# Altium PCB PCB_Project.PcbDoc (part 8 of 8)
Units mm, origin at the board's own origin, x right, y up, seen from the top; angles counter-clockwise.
Board outline 250 x 200 mm, 6 copper layers (Top Shielding/Sig, Sig 1, PWR, GND, Sig 4, Bottom Shielding/Sig), stack 1.568 mm thick; 736 components, 420 nets, 1929 pads, 2185 vias.
Unrouted connection lines stored in the file: 47.
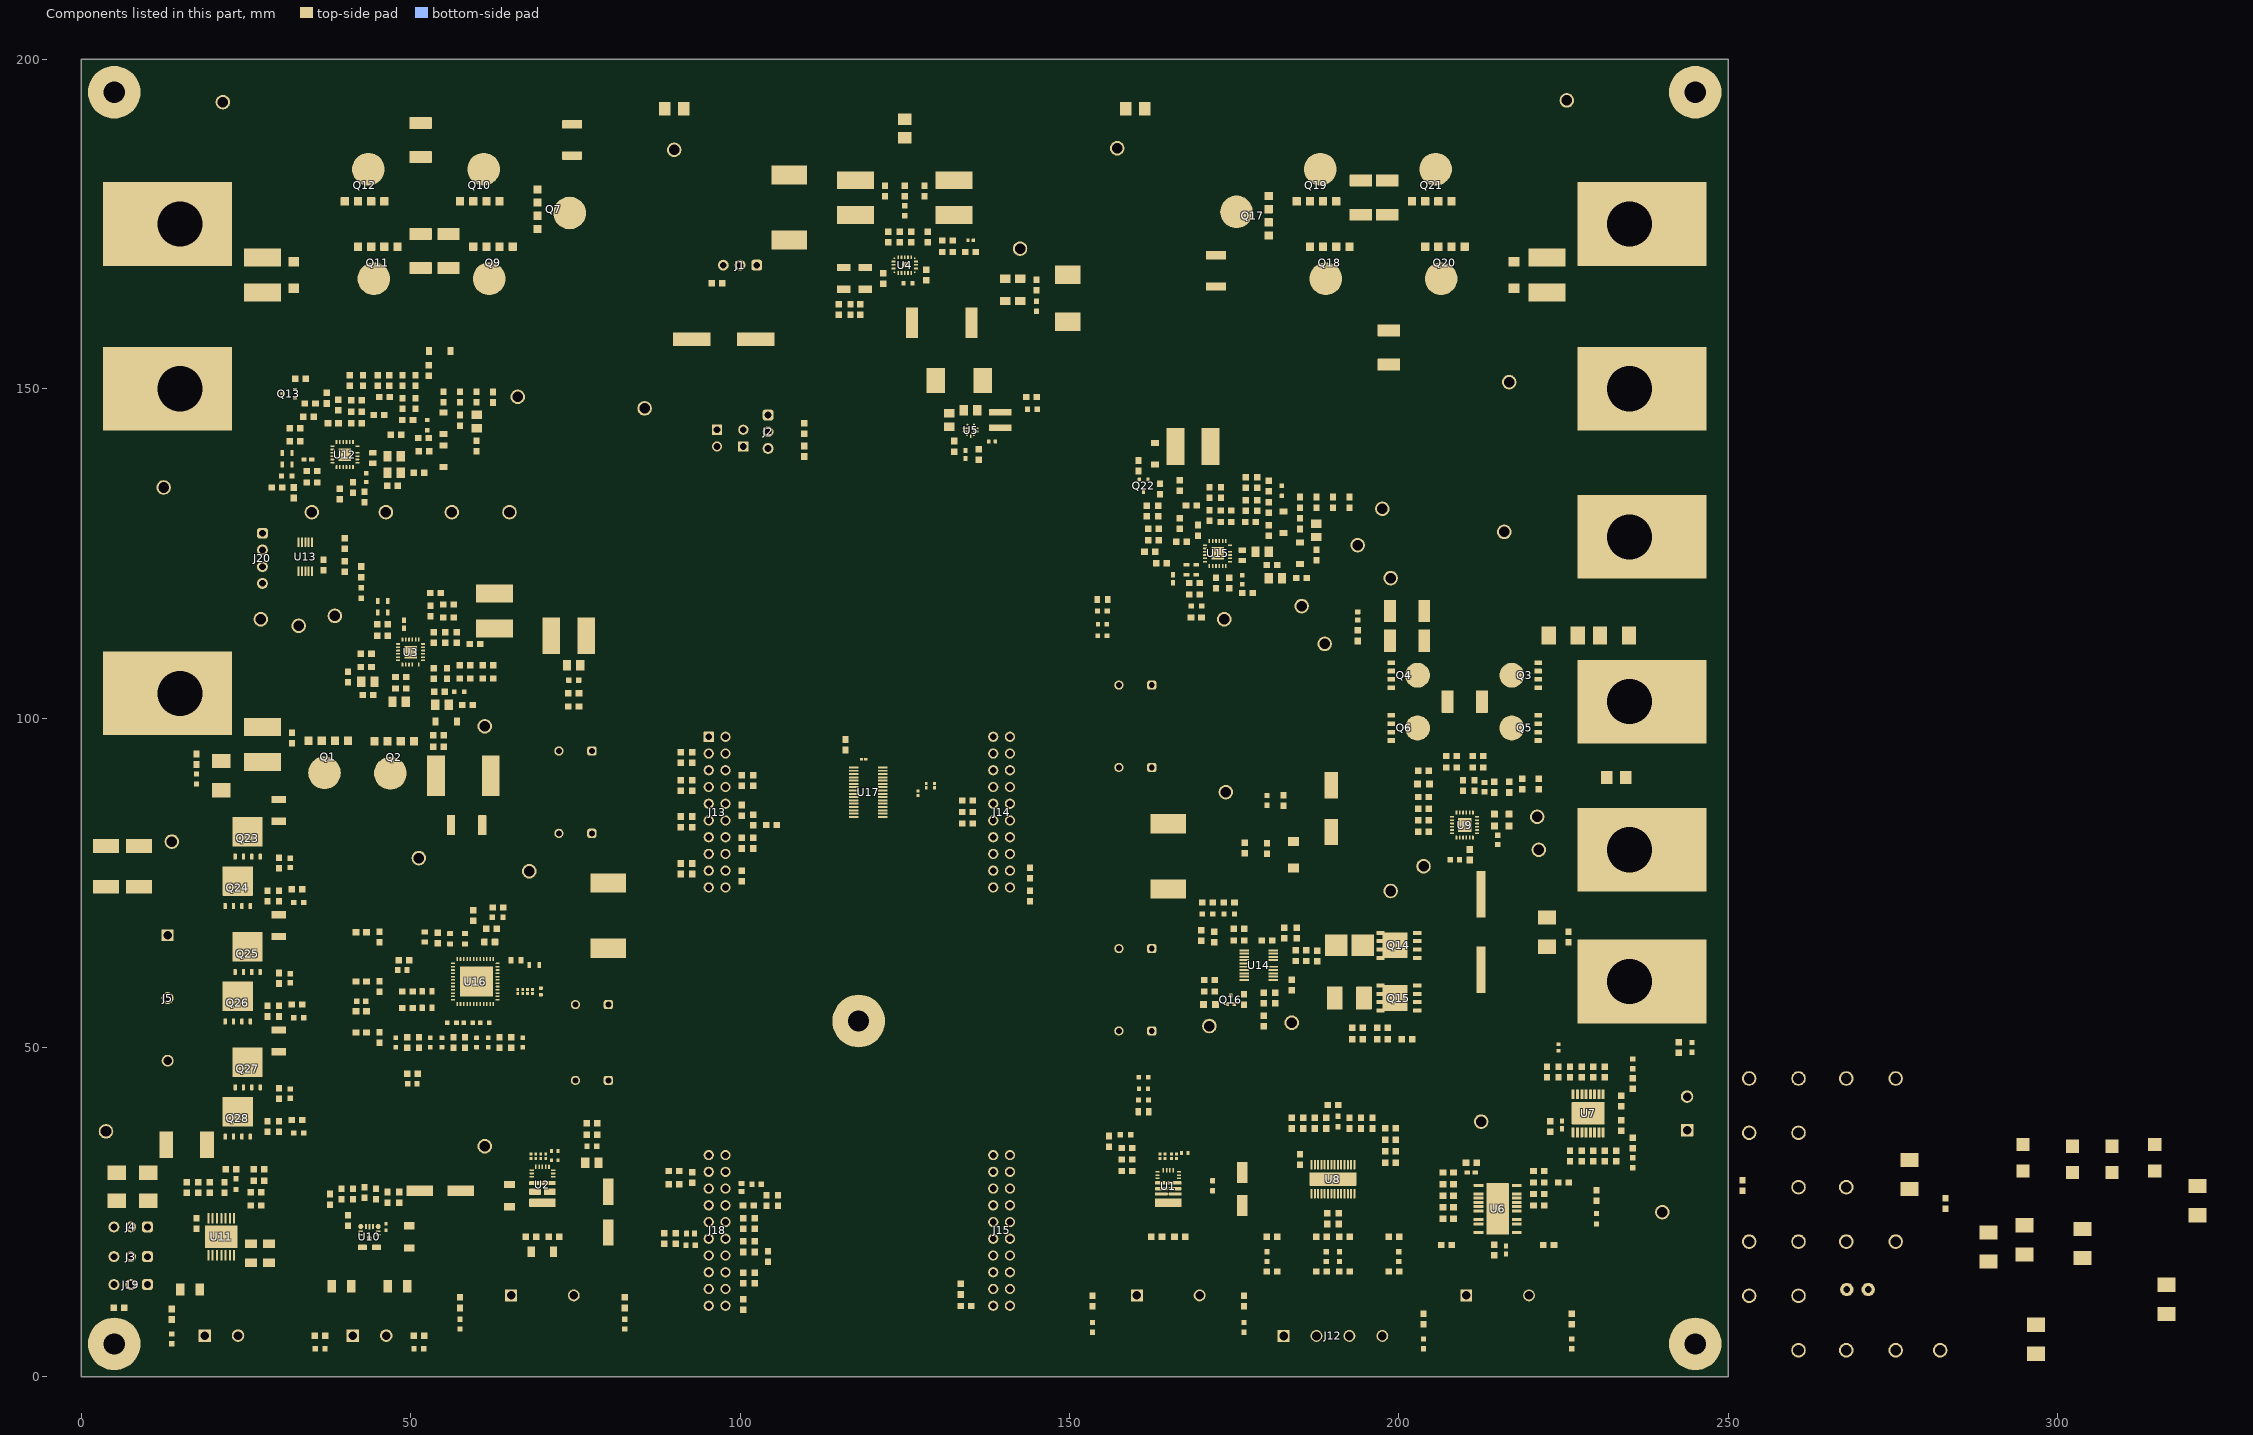
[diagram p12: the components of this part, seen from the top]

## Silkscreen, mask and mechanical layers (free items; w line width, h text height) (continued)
Drill Drawing:
  circle w0.254: c308.533,64.587 r0.702
  circle w0.254: c308.533,61.429 r0.421
  circle w0.254: c308.533,61.429 r0.702
  lines w0.254: 307.831,67.394 308.182,67.394 308.533,67.043 308.883,67.394 309.234,67.394 308.883,67.744 309.234,68.095 308.883,68.095 308.533,68.446 308.182,68.095 307.831,68.095 308.182,67.744 307.831,67.394 ; 307.831,70.201 309.234,70.201 309.234,71.604 307.831,71.604 307.831,70.201 ; 307.831,74.06 308.533,73.358 309.234,74.06 308.533,74.762 307.831,74.06 ; 307.831,76.867 308.182,76.867 308.182,76.516 308.883,76.516 308.883,76.867 309.234,76.867 309.234,77.569 308.883,77.569 308.883,77.919 308.182,77.919 308.182,77.569 307.831,77.569 307.831,76.867 ; 307.831,79.674 308.533,80.025 309.234,79.674 308.883,80.375 309.234,81.077 308.533,80.726 307.831,81.077 308.182,80.375 307.831,79.674 ; 307.831,84.235 309.234,84.235 308.533,82.831 307.831,84.235 ; 307.831,85.989 308.533,86.34 309.234,85.989 308.883,86.691 309.234,87.393 308.533,87.042 307.831,87.393 308.182,86.691 307.831,85.989 ; 307.831,89.498 308.182,89.498 308.533,89.147 308.883,89.498 309.234,89.498 308.883,89.849 309.234,90.199 308.883,90.199 308.533,90.55 308.182,90.199 307.831,90.199 308.182,89.849 307.831,89.498 ; 307.831,92.305 309.234,92.305 309.234,93.708 307.831,93.708 307.831,92.305 ; 307.831,96.866 309.234,96.866 308.533,95.462 307.831,96.866 ; 308.112,70.481 308.954,70.481 308.954,71.323 308.112,71.323 308.112,70.481 ; 308.112,86.27 308.533,86.48 308.954,86.27 308.743,86.691 308.954,87.112 308.533,86.901 308.112,87.112 308.322,86.691 308.112,86.27 ; 308.112,89.638 308.322,89.638 308.533,89.428 308.743,89.638 308.954,89.638 308.743,89.849 308.954,90.059 308.743,90.059 308.533,90.27 308.322,90.059 308.112,90.059 308.322,89.849 308.112,89.638 ; 308.112,96.585 308.954,96.585 308.533,95.743 308.112,96.585
  lines w0.305: 306.559,59.78 398.539,59.78 ; 306.559,97.673 398.539,97.673 ; 315.14,56.622 315.14,100.83 ; 323.577,56.622 323.577,100.83 ; 339.746,56.622 339.746,100.83 ; 346.328,56.622 346.328,100.83 ; 355.857,56.622 355.857,100.83 ; 384.151,56.622 384.151,100.83 ; 306.559,56.622 398.539,56.622 398.539,100.83 306.559,100.83 306.559,56.622
  text "Symbol" at 308.453,98.62 h1.83
  text "Quantity" at 316.088,98.62 h1.83
  text "Finished Hole Size" at 324.525,98.62 h1.83
  text "Plated" at 340.693,98.62 h1.83
  text "Hole Type" at 347.275,98.62 h1.83
  text "Drill Layer Pair" at 356.805,98.62 h1.83
  text "Hole Tolerance" at 385.099,98.62 h1.83
  text "137" at 316.088,95.462 h1.52
  text "7.87mil (0.200mm)" at 324.525,95.462 h1.52
  text "PTH" at 340.693,95.462 h1.52
  text "Round" at 347.275,95.462 h1.52
  text "Top Shielding/Sig - Bottom Shielding/Sig" at 356.805,95.462 h1.52
  text "1520" at 316.088,92.305 h1.52
  text "10.00mil (0.254mm)" at 324.525,92.305 h1.52
  text "PTH" at 340.693,92.305 h1.52
  text "Round" at 347.275,92.305 h1.52
  text "Top Shielding/Sig - Bottom Shielding/Sig" at 356.805,92.305 h1.52
  text "6" at 316.088,89.147 h1.52
  text "12.99mil (0.330mm)" at 324.525,89.147 h1.52
  text "PTH" at 340.693,89.147 h1.52
  text "Round" at 347.275,89.147 h1.52
  text "Top Shielding/Sig - Bottom Shielding/Sig" at 356.805,89.147 h1.52
  text "522" at 316.088,85.989 h1.52
  text "16.00mil (0.406mm)" at 324.525,85.989 h1.52
  text "PTH" at 340.693,85.989 h1.52
  text "Round" at 347.275,85.989 h1.52
  text "Top Shielding/Sig - Bottom Shielding/Sig" at 356.805,85.989 h1.52
  text "16" at 316.088,82.831 h1.52
  text "35.43mil (0.900mm)" at 324.525,82.831 h1.52
  text "PTH" at 340.693,82.831 h1.52
  text "Round" at 347.275,82.831 h1.52
  text "Top Shielding/Sig - Bottom Shielding/Sig" at 356.805,82.831 h1.52
  text "19" at 316.088,79.674 h1.52
  text "40.00mil (1.016mm)" at 324.525,79.674 h1.52
  text "PTH" at 340.693,79.674 h1.52
  text "Round" at 347.275,79.674 h1.52
  text "Top Shielding/Sig - Bottom Shielding/Sig" at 356.805,79.674 h1.52
  text "84" at 316.088,76.516 h1.52
  text "40.16mil (1.020mm)" at 324.525,76.516 h1.52
  text "PTH" at 340.693,76.516 h1.52
  text "Round" at 347.275,76.516 h1.52
  text "Top Shielding/Sig - Bottom Shielding/Sig" at 356.805,76.516 h1.52
  text "10" at 316.088,73.358 h1.52
  text "51.18mil (1.300mm)" at 324.525,73.358 h1.52
  text "PTH" at 340.693,73.358 h1.52
  text "Round" at 347.275,73.358 h1.52
  text "Top Shielding/Sig - Bottom Shielding/Sig" at 356.805,73.358 h1.52
  text "9" at 316.088,70.201 h1.52
  text "51.18mil (1.300mm)" at 324.525,70.201 h1.52
  text "PTH" at 340.693,70.201 h1.52
  text "Round" at 347.275,70.201 h1.52
  text "Top Shielding/Sig - Bottom Shielding/Sig" at 356.805,70.201 h1.52
  text "+/-3.94mil" at 385.099,70.201 h1.52
  text "38" at 316.088,67.043 h1.52
  text "63.00mil (1.600mm)" at 324.525,67.043 h1.52
  text "PTH" at 340.693,67.043 h1.52
  text "Round" at 347.275,67.043 h1.52
  text "Top Shielding/Sig - Bottom Shielding/Sig" at 356.805,67.043 h1.52
  text "5" at 316.088,63.885 h1.52
  text "125.98mil (3.200mm)" at 324.525,63.885 h1.52
  text "PTH" at 340.693,63.885 h1.52
  text "Round" at 347.275,63.885 h1.52
  text "Top Shielding/Sig - Bottom Shielding/Sig" at 356.805,63.885 h1.52
  text "9" at 316.088,60.727 h1.52
  text "270.00mil (6.858mm)" at 324.525,60.727 h1.52
  text "PTH" at 340.693,60.727 h1.52
  text "Round" at 347.275,60.727 h1.52
  text "Top Shielding/Sig - Bottom Shielding/Sig" at 356.805,60.727 h1.52
  text "2375 Total" at 316.088,57.57 h1.52
  text ".Layer_Name" at 10.656,-21.806 h1.52
M17 Grids:
  lines w0.305: 49,1.5 225,1.5 ; 88.9,33.655 95.25,33.655 ; 95.25,33.651 95.25,97.151 138.43,97.151 ; 97.79,33.655 138.43,74.295 138.43,65.68 ; 97.79,74.295 138.43,33.655 ; 120.65,0 120.65,33.655 ; 125,0 125,200 ; 138.43,97.155 138.43,33.655 ; 140.97,33.655 147.32,33.655 ; 95.25,33.655 138.43,33.655 ; 95.25,33.655 138.43,33.655
  text ".Layer_Name" at 10.656,-21.806 h1.52
M18 Embedded Assembly:
  text ".Layer_Name" at 10.656,-21.806 h1.52
M19 Embedded Keepout:
  text ".Layer_Name" at 10.656,-21.806 h1.52

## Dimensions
250,-0.5 to 0,-0.5 on M2 Board Dimensions
0,-9.66 to 25.4,-9.66 on M2 Board Dimensions
-0.5,0 to -0.5,200 on M2 Board Dimensions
